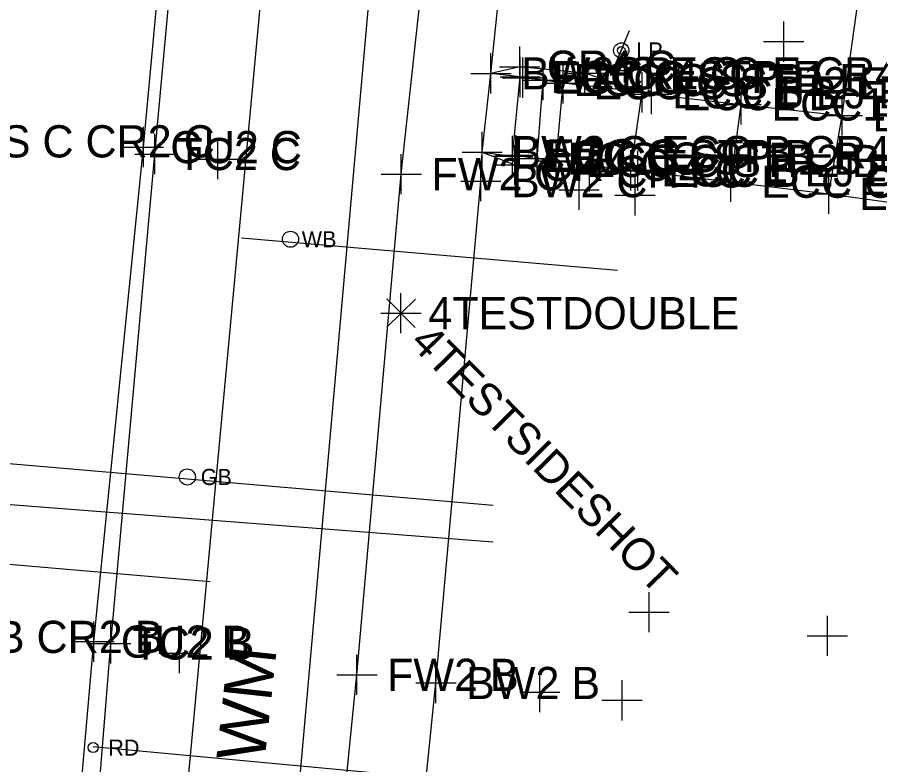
# Model space of a CAD drawing. Extents: x 1363693 to 1365209, y 422201 to 424153.
# Drawn here: x 1364260.16 to 1364303.02, y 423181.98 to 423219.14 of the extents above; entities that cross this region are included whole.
import ezdxf

# ---------------------------------------------------------------- set-up
doc = ezdxf.new("R2010")
doc.units = 0
for name, color, linetype in [('BASELINE-CL-RW', 7, 'Continuous'), ('DR_X_Cells', 7, 'Continuous'), ('DR_X_Drive_Pipe', 7, 'Continuous'), ('DR_X_Text', 7, 'Continuous'), ('O-ALGN-BASELINE-WERK-CL-RW', 7, 'Continuous'), ('O-ALGN-TEXT-BASELINE-WERK-CL-RW', 7, 'Continuous'), ('OWNERS', 7, 'Continuous'), ('PV_X_Driveway', 7, 'Continuous'), ('PV_X_Joint', 7, 'Continuous'), ('RD_X_Misc_Items', 7, 'Continuous'), ('RD_X_Text', 7, 'Continuous'), ('SV_X_Original_Ground', 7, 'Continuous'), ('SV_X_Shot_Marker', 7, 'Continuous'), ('UT_X_Gas', 7, 'Continuous'), ('UT_X_Gas_Cells', 7, 'Continuous'), ('UT_X_Gas_Text', 7, 'Continuous'), ('UT_X_Telecom', 7, 'Continuous'), ('UT_X_Water', 7, 'Continuous'), ('UT_X_Water_Text', 7, 'Continuous')]:
    doc.layers.add(name, color=color, linetype=linetype)

msp = doc.modelspace()

# ---------------------------------------------------------------- linework, layer by layer
at = {"layer": 'BASELINE-CL-RW'}
for points in [[(1364264.815, 423188.013), (1364267.006, 423212.341), (1364268.256, 423226.071), (1364268.539, 423228.461)], [(1364267.706, 423142.781), (1364267.082, 423144.327), (1364267.082, 423144.327), (1364266.388, 423146.082), (1364264.482, 423150.153), (1364263.239, 423154.472), (1364263.239, 423154.472), (1364262.707, 423158.575), (1364262.774, 423162.712), (1364262.774, 423162.712), (1364264.815, 423188.013)]]:
    msp.add_lwpolyline(points, dxfattribs=at)
at = {"layer": 'DR_X_Cells'}
msp.add_circle((1364263.939, 423182.837), 0.25, dxfattribs=at)
at = {"layer": 'DR_X_Drive_Pipe'}
msp.add_line((1364263.931, 423182.896), (1364289.467, 423180.521), dxfattribs=at)
at = {"layer": 'O-ALGN-BASELINE-WERK-CL-RW'}
for points in [[(1364291.211, 423215.409), (1364288.372, 423216.354), (1364285.135, 423216.681), (1364283.699, 423216.351)], [(1364283.267, 423212.437), (1364284.89, 423211.803), (1364288.603, 423211.473), (1364290.651, 423211.532)]]:
    msp.add_lwpolyline(points, dxfattribs=at)
at = {"layer": 'O-ALGN-TEXT-BASELINE-WERK-CL-RW'}
for points in [[(1364277.041, 423186.453), (1364279.249, 423211.34), (1364281.062, 423228.074), (1364281.809, 423236.125), (1364283.024, 423250.18), (1364284.121, 423261.072), (1364286.393, 423285.925), (1364288.893, 423310.853), (1364289.461, 423315.932), (1364291.285, 423335.668), (1364291.825, 423341.593), (1364293.598, 423360.72), (1364295.788, 423384.44), (1364295.973, 423385.791), (1364296.712, 423394.509), (1364298.068, 423410.324), (1364299.056, 423420.392), (1364298.963, 423423.182), (1364298.651, 423425.956), (1364298.651, 423425.956), (1364298.044, 423429.016), (1364297.169, 423432.011), (1364297.169, 423432.011)], [(1364280.967, 423186.048), (1364283.2, 423210.994), (1364283.267, 423212.437), (1364283.699, 423216.351), (1364285.121, 423230.045), (1364285.744, 423235.895), (1364286.966, 423249.699), (1364288.049, 423260.634), (1364290.333, 423285.623)], [(1364267.082, 423144.327), (1364269.373, 423145.027), (1364273.22, 423146.258), (1364274.556, 423161.646), (1364277.041, 423186.453)], [(1364321.549, 423126.841), (1364296.522, 423129.399), (1364291.593, 423129.917), (1364288.303, 423133.628), (1364283.795, 423138.603), (1364279.64, 423143.27), (1364277.256, 423145.997), (1364278.44, 423161.186), (1364280.967, 423186.048)]]:
    msp.add_lwpolyline(points, dxfattribs=at)
at = {"layer": 'OWNERS'}
for p, q in [((1364284.777, 423212.243), (1364285.153, 423216.171)), ((1364286.002, 423212.114), (1364286.303, 423216.019)), ((1364286.943, 423211.999), (1364287.289, 423215.859))]:
    msp.add_line(p, q, dxfattribs=at)
for points in [[(1364263.974, 423188.104), (1364266.432, 423212.687), (1364267.926, 423228.81), (1364268.734, 423237.459), (1364270.156, 423253.843), (1364270.935, 423262.642), (1364273.302, 423287.489), (1364275.861, 423312.256), (1364278.117, 423337.291), (1364278.887, 423344.525), (1364280.523, 423362.288), (1364282.564, 423384.505), (1364282.845, 423386.962), (1364283.643, 423396.734), (1364284.072, 423402.846), (1364284.5, 423405.767)], [(1364291.211, 423215.409), (1364287.289, 423215.859), (1364286.303, 423216.019), (1364285.279, 423216.134), (1364285.153, 423216.171), (1364283.699, 423216.351)], [(1364283.267, 423212.437), (1364284.777, 423212.243), (1364284.933, 423212.279), (1364286.002, 423212.114), (1364286.943, 423211.999), (1364290.651, 423211.532)], [(1364265.763, 423145.848), (1364263.949, 423150.02), (1364262.666, 423154.384), (1364262.666, 423154.384), (1364261.973, 423158.501), (1364261.754, 423162.67), (1364261.754, 423162.67), (1364263.974, 423188.104)]]:
    msp.add_lwpolyline(points, dxfattribs=at)
at = {"layer": 'PV_X_Driveway'}
for p, q in [((1364284.777, 423212.243), (1364285.153, 423216.171)), ((1364286.002, 423212.114), (1364286.303, 423216.019)), ((1364286.943, 423211.999), (1364287.289, 423215.859))]:
    msp.add_line(p, q, dxfattribs=at)
for points in [[(1364291.68, 423215.321), (1364296.135, 423214.804), (1364301.16, 423214.262), (1364302.09, 423221.069), (1364302.853, 423228.374), (1364299.752, 423228.735)], [(1364291.211, 423215.409), (1364287.289, 423215.859), (1364286.303, 423216.019), (1364285.279, 423216.134), (1364285.153, 423216.171), (1364283.699, 423216.351)], [(1364283.267, 423212.437), (1364284.777, 423212.243), (1364284.933, 423212.279), (1364286.002, 423212.114), (1364286.943, 423211.999), (1364290.651, 423211.532)], [(1364291.005, 423211.506), (1364295.628, 423210.966), (1364300.494, 423210.365), (1364304.426, 423209.818), (1364304.57, 423209.424), (1364305.542, 423209.336), (1364306.518, 423209.217), (1364307.391, 423209.093)]]:
    msp.add_lwpolyline(points, dxfattribs=at)
at = {"layer": 'PV_X_Joint'}
for p, q in [((1364290.651, 423211.532), (1364291.211, 423215.409)), ((1364295.628, 423210.966), (1364296.135, 423214.804)), ((1364300.494, 423210.365), (1364301.16, 423214.262))]:
    msp.add_line(p, q, dxfattribs=at)
at = {"layer": 'RD_X_Misc_Items'}
for p, q in [((1364289.765, 423216.489), (1364290.591, 423218.489)), ((1364289.972, 423216.989), (1364290.384, 423217.989)), ((1364289.972, 423216.989), (1364290.312, 423216.989)), ((1364289.765, 423216.489), (1364290.446, 423216.489))]:
    msp.add_line(p, q, dxfattribs=at)
for radius in [0.38, 0.19]:
    msp.add_circle((1364290.178, 423217.489), radius, dxfattribs=at)
at = {"layer": 'SV_X_Original_Ground'}
for p, q in [((1364298.251, 423216.928), (1364298.251, 423218.928)), ((1364297.251, 423217.928), (1364299.251, 423217.928)), ((1364285.135, 423215.681), (1364285.135, 423217.681)), ((1364288.372, 423215.354), (1364288.372, 423217.354)), ((1364284.135, 423216.681), (1364286.135, 423216.681)), ((1364287.372, 423216.354), (1364289.372, 423216.354)), ((1364270.125, 423211.087), (1364270.125, 423213.087)), ((1364284.89, 423210.803), (1364284.89, 423212.803)), ((1364288.603, 423210.473), (1364288.603, 423212.473)), ((1364269.125, 423212.087), (1364271.125, 423212.087)), ((1364283.89, 423211.803), (1364285.89, 423211.803)), ((1364287.603, 423211.473), (1364289.603, 423211.473)), ((1364288.079, 423209.564), (1364288.079, 423211.564)), ((1364290.863, 423209.294), (1364290.863, 423211.294)), ((1364287.079, 423210.564), (1364289.079, 423210.564)), ((1364289.863, 423210.294), (1364291.863, 423210.294)), ((1364279.231, 423203.431), (1364279.231, 423205.431)), ((1364278.521, 423203.729), (1364279.947, 423205.131)), ((1364278.533, 423205.143), (1364279.935, 423203.717)), ((1364278.231, 423204.431), (1364280.231, 423204.431)), ((1364291.557, 423188.57), (1364291.557, 423190.57)), ((1364290.557, 423189.57), (1364292.557, 423189.57)), ((1364300.418, 423187.392), (1364300.418, 423189.392)), ((1364268.221, 423186.538), (1364268.221, 423188.538)), ((1364299.418, 423188.392), (1364301.418, 423188.392)), ((1364267.221, 423187.538), (1364269.221, 423187.538)), ((1364286.131, 423184.599), (1364286.131, 423186.599)), ((1364290.22, 423184.189), (1364290.22, 423186.189)), ((1364285.131, 423185.599), (1364287.131, 423185.599)), ((1364289.22, 423185.189), (1364291.22, 423185.189))]:
    msp.add_line(p, q, dxfattribs=at)
at = {"layer": 'SV_X_Shot_Marker'}
for p, q in [((1364283.699, 423215.351), (1364283.699, 423217.351)), ((1364285.153, 423215.171), (1364285.153, 423217.171)), ((1364285.279, 423215.134), (1364285.279, 423217.134)), ((1364286.303, 423215.019), (1364286.303, 423217.019)), ((1364287.289, 423214.859), (1364287.289, 423216.859)), ((1364282.699, 423216.351), (1364284.699, 423216.351)), ((1364284.153, 423216.171), (1364286.153, 423216.171)), ((1364284.279, 423216.134), (1364286.279, 423216.134)), ((1364291.211, 423214.409), (1364291.211, 423216.409)), ((1364291.68, 423214.321), (1364291.68, 423216.321)), ((1364285.303, 423216.019), (1364287.303, 423216.019)), ((1364286.289, 423215.859), (1364288.289, 423215.859)), ((1364296.135, 423213.804), (1364296.135, 423215.804)), ((1364290.211, 423215.409), (1364292.211, 423215.409)), ((1364290.68, 423215.321), (1364292.68, 423215.321)), ((1364301.16, 423213.262), (1364301.16, 423215.262)), ((1364295.135, 423214.804), (1364297.135, 423214.804)), ((1364300.16, 423214.262), (1364302.16, 423214.262)), ((1364266.432, 423211.687), (1364266.432, 423213.687)), ((1364267.006, 423211.341), (1364267.006, 423213.341)), ((1364283.267, 423211.437), (1364283.267, 423213.437)), ((1364284.777, 423211.243), (1364284.777, 423213.243)), ((1364284.933, 423211.279), (1364284.933, 423213.279)), ((1364286.002, 423211.114), (1364286.002, 423213.114)), ((1364286.943, 423210.999), (1364286.943, 423212.999)), ((1364265.432, 423212.687), (1364267.432, 423212.687)), ((1364266.006, 423212.341), (1364268.006, 423212.341)), ((1364279.249, 423210.34), (1364279.249, 423212.34)), ((1364282.267, 423212.437), (1364284.267, 423212.437)), ((1364283.933, 423212.279), (1364285.933, 423212.279)), ((1364290.651, 423210.532), (1364290.651, 423212.532)), ((1364291.005, 423210.506), (1364291.005, 423212.506)), ((1364283.2, 423209.994), (1364283.2, 423211.994)), ((1364283.777, 423212.243), (1364285.777, 423212.243)), ((1364285.002, 423212.114), (1364287.002, 423212.114)), ((1364285.943, 423211.999), (1364287.943, 423211.999)), ((1364295.628, 423209.966), (1364295.628, 423211.966)), ((1364289.651, 423211.532), (1364291.651, 423211.532)), ((1364290.005, 423211.506), (1364292.005, 423211.506)), ((1364278.249, 423211.34), (1364280.249, 423211.34)), ((1364282.2, 423210.994), (1364284.2, 423210.994)), ((1364300.494, 423209.365), (1364300.494, 423211.365)), ((1364294.628, 423210.966), (1364296.628, 423210.966)), ((1364299.494, 423210.365), (1364301.494, 423210.365)), ((1364263.974, 423187.104), (1364263.974, 423189.104)), ((1364264.815, 423187.013), (1364264.815, 423189.013)), ((1364262.974, 423188.104), (1364264.974, 423188.104)), ((1364263.815, 423188.013), (1364265.815, 423188.013)), ((1364277.041, 423185.453), (1364277.041, 423187.453)), ((1364280.967, 423185.048), (1364280.967, 423187.048)), ((1364276.041, 423186.453), (1364278.041, 423186.453)), ((1364279.967, 423186.048), (1364281.967, 423186.048))]:
    msp.add_line(p, q, dxfattribs=at)
at = {"layer": 'UT_X_Gas'}
for p, q in [((1364283.81, 423194.875), (1364223.033, 423200.094)), ((1364222.83, 423197.797), (1364283.81, 423193.059))]:
    msp.add_line(p, q, dxfattribs=at)
at = {"layer": 'UT_X_Gas_Cells'}
msp.add_circle((1364268.613, 423196.289), 0.4, dxfattribs=at)
at = {"layer": 'UT_X_Telecom'}
msp.add_lwpolyline([(1364331.133, 423132.499), (1364271.573, 423151.567), (1364307.701, 423558.666)], dxfattribs=at)
at = {"layer": 'UT_X_Water'}
for p, q in [((1364271.311, 423208.17), (1364289.994, 423206.561)), ((1364208.969, 423196.336), (1364269.751, 423191.101))]:
    msp.add_line(p, q, dxfattribs=at)
msp.add_lwpolyline([(1364264.276, 423134.188), (1364290.904, 423420.252), (1364296.496, 423480.942), (1364304.106, 423560.043)], dxfattribs=at)
msp.add_circle((1364273.741, 423208.104), 0.4, dxfattribs=at)

# ---------------------------------------------------------------- texts
at = {"layer": 'DR_X_Text'}
msp.add_text('RD', height=0.8, dxfattribs=at).set_placement((1364264.689, 423182.437))
at = {"layer": 'RD_X_Text'}
msp.add_text('LP', height=0.8, dxfattribs=at).set_placement((1364290.928, 423217.089))
at = {"layer": 'SV_X_Original_Ground'}
for s, p in [('CR4 C', (1364286.472, 423215.881)), ('CR4 C', (1364289.709, 423215.554)), ('DYS C CR2 C', (1364256.423, 423212.172)), ('CR4 C', (1364286.227, 423211.003)), ('CR4 C', (1364289.94, 423210.673)), ('4TESTDOUBLE', (1364280.588, 423203.631)), ('DYS B CR2 B', (1364254.107, 423187.539))]:
    msp.add_text(s, height=1.6, dxfattribs=at).set_placement(p)
msp.add_text('4TESTSIDESHOT', height=1.6, rotation=314.527, dxfattribs=at).set_placement((1364279.615, 423202.902))
at = {"layer": 'SV_X_Shot_Marker'}
for s, p in [('BW2 C ECC E CR4 E', (1364285.199, 423215.551)), ('ECC C STP E', (1364286.653, 423215.371)), ('ECC C', (1364286.779, 423215.334)), ('ECC C STP1 E', (1364287.803, 423215.219)), ('ECC C STP2 E', (1364288.789, 423215.059)), ('ECC B EJ E CR4 B', (1364292.711, 423214.609)), ('ECC1 B', (1364293.18, 423214.521)), ('ECC1 C EJ E', (1364297.635, 423214.004)), ('ECC1 C EJ1 E', (1364302.66, 423213.462)), ('GU2 C', (1364267.769, 423211.887)), ('TC2 C', (1364268.077, 423211.541)), ('BW2 C ECC B CR4 B', (1364284.767, 423211.637)), ('ECC C STP B', (1364286.277, 423211.443)), ('ECC C', (1364286.433, 423211.479)), ('ECC C STP1 B', (1364287.502, 423211.314)), ('ECC C STP2 B', (1364288.443, 423211.199)), ('ECC E EJ B CR4 E', (1364292.151, 423210.732)), ('ECC B', (1364292.505, 423210.706)), ('FW2 C', (1364280.749, 423210.54)), ('BW2 C', (1364284.7, 423210.194)), ('ECC C EJ B', (1364297.128, 423210.166)), ('ECC C EJ1 B', (1364301.994, 423209.565)), ('GU2 B', (1364265.311, 423187.304)), ('TC2 B', (1364265.886, 423187.213)), ('FW2 B', (1364278.541, 423185.653)), ('BW2 B', (1364282.467, 423185.248))]:
    msp.add_text(s, height=1.6, dxfattribs=at).set_placement(p)
at = {"layer": 'UT_X_Gas_Text'}
msp.add_text('GB', height=0.8, dxfattribs=at).set_placement((1364269.281, 423195.889))
at = {"layer": 'UT_X_Water_Text'}
msp.add_text('WB', height=0.8, dxfattribs=at).set_placement((1364274.301, 423207.704))
msp.add_text('EX. 8" WM', height=2.4, rotation=83.8006, dxfattribs=at).set_placement((1364271.378, 423172.248))

doc.saveas('drawing.dxf')
